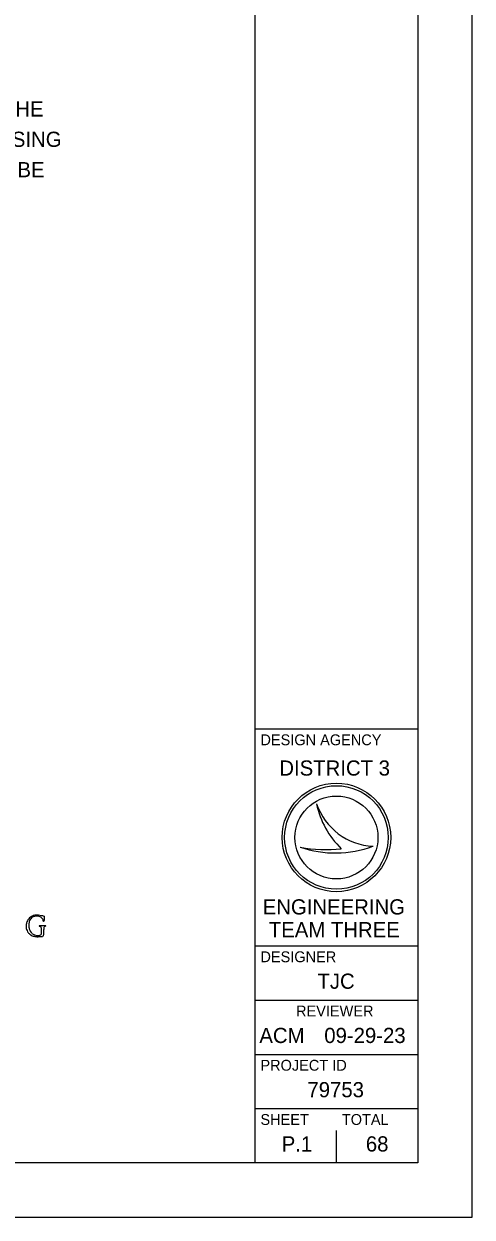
# Model space of a CAD drawing. Extents: x 0 to 34, y 0 to 22.
# Drawn here: x 29.87 to 34, y 0 to 11 of the extents above; entities that cross this region are included whole.
import ezdxf

# ---------------------------------------------------------------- set-up
doc = ezdxf.new("R2010")
doc.units = 0
for name, color, linetype in [('SH_Border', 7, 'Continuous'), ('SH_Cut_Line', 7, 'Continuous'), ('SH_Data', 7, 'Continuous'), ('SH_Text', 7, 'Continuous')]:
    doc.layers.add(name, color=color, linetype=linetype)

msp = doc.modelspace()

# ---------------------------------------------------------------- linework, layer by layer
at = {"layer": 'SH_Border'}
for p, q in [((32, 0.5), (32, 21.5)), ((32, 4.5), (33.5, 4.5)), ((32, 2.5), (33.5, 2.5)), ((32, 2), (33.5, 2)), ((32, 1.5), (33.5, 1.5)), ((32, 1), (33.5, 1))]:
    msp.add_line(p, q, dxfattribs=at)
msp.add_lwpolyline([(1.5, 21.5), (33.5, 21.5), (33.5, 0.5), (1.5, 0.5)], close=True, dxfattribs=at)
at = {"layer": 'SH_Cut_Line'}
msp.add_lwpolyline([(0, 0), (34, 0), (34, 22), (0, 22)], close=True, dxfattribs=at)
at = {"layer": 'SH_Data'}
for p, q in [((32.567, 3.81), (32.567, 3.81)), ((32.75, 3.5), (32.75, 3.5)), ((33.087, 3.419), (33.087, 3.419)), ((32.417, 3.41), (32.417, 3.41)), ((32.75, 0.5), (32.75, 0.8)), ((32.375, 0.675), (32.375, 0.675))]:
    msp.add_line(p, q, dxfattribs=at)
for radius in [0.5, 0.477, 0.477, 0.382]:
    msp.add_circle((32.75, 3.5), radius, dxfattribs=at)
for centre, radius, start, end in [((33.116, 3.998), 0.58, 198.9257, 198.9319), ((33.347, 3.97), 0.796, 191.6379, 191.6421), ((33.116, 3.998), 0.58, 198.9319, 267.1657), ((33.347, 3.97), 0.796, 191.6421, 226.0947), ((32.739, 4.37), 1.013, 251.4576, 290.0832), ((32.648, 4.654), 1.266, 259.4964, 259.4995), ((32.739, 4.37), 1.013, 251.4527, 251.4576), ((32.648, 4.654), 1.266, 259.4995, 276.6672)]:
    msp.add_arc(centre, radius, start, end, dxfattribs=at)
at = {"layer": 'SH_Text'}
for p, q in [((30.072, 2.685), (30.014, 2.685)), ((30.031, 2.666), (30.031, 2.61)), ((30.054, 2.605), (30.054, 2.652))]:
    msp.add_line(p, q, dxfattribs=at)
for centre, radius, start, end in [((30.005, 2.676), 0.116, 135.2994, 157.2066), ((29.985, 2.697), 0.0867, 107.613, 135.2994), ((29.989, 2.705), 0.0714, 116.7026, 147.5385), ((29.983, 2.716), 0.0589, 93.5922, 116.7026), ((29.986, 2.692), 0.0916, 90.0889, 107.613), ((29.99, 2.603), 0.172, 87.6816, 93.5922), ((29.986, 2.53), 0.254, 85.6243, 90.0889), ((29.995, 2.724), 0.0509, 59.809, 87.6816), ((29.987, 2.54), 0.243, 73.3259, 85.6243), ((29.962, 2.667), 0.117, 52.0865, 59.809), ((30.01, 2.729), 0.0384, 2.9119, 52.0865), ((30.056, 2.769), 0.00494, 1.0594, 73.3259), ((29.858, 2.765), 0.203, 350.1479, 1.0594), ((29.983, 2.681), 0.0913, 176.8679, 187.4835), ((30.032, 2.678), 0.141, 167.8164, 176.8679), ((29.97, 2.679), 0.0789, 187.4835, 199.5864), ((29.961, 2.694), 0.0685, 158.442, 167.8164), ((30.038, 2.703), 0.151, 199.5864, 208.6065), ((30.005, 2.676), 0.116, 157.2066, 158.442), ((30.058, 2.688), 0.142, 167.8795, 178.2857), ((30.014, 2.69), 0.0979, 178.2857, 190.5998), ((30.148, 2.715), 0.235, 190.5998, 194.5022), ((30.025, 2.696), 0.108, 165.5071, 167.8795), ((29.989, 2.705), 0.0714, 147.5385, 165.5071), ((30, 2.677), 0.0818, 194.5022, 227.8932), ((30.014, 2.683), 0.00203, 90, 277.32), ((30.016, 2.666), 0.0146, 0, 97.32), ((30.053, 2.731), 0.00447, 182.9119, 350.1479), ((30.213, 2.652), 0.159, 172.0456, 180), ((30.062, 2.674), 0.00585, 114.8736, 172.0456), ((30.069, 2.657), 0.0242, 95.8947, 114.8736), ((30.085, 2.508), 0.174, 94.3316, 95.8947), ((30.072, 2.683), 0.00179, 274.3316, 90), ((29.977, 2.67), 0.0815, 208.6065, 229.3453), ((29.999, 2.696), 0.115, 229.3453, 237.7571), ((29.974, 2.657), 0.0686, 237.7571, 254.2366), ((29.996, 2.672), 0.0755, 227.8932, 268.7516), ((29.992, 2.72), 0.134, 254.2366, 269.1033), ((29.995, 2.891), 0.306, 269.1033, 278.6618), ((29.996, 2.671), 0.075, 268.7516, 293.6665), ((30.023, 2.61), 0.00829, 293.6665, 0), ((30.038, 2.605), 0.016, 278.6618, 0)]:
    msp.add_arc(centre, radius, start, end, dxfattribs=at)

# ---------------------------------------------------------------- texts
at = {"layer": 'SH_Data'}
for s, height, p in [('DESIGN AGENCY', 0.1, (32.05, 4.35)), ('DISTRICT 3', 0.14, (32.224, 4.07)), ('ENGINEERING', 0.14, (32.071, 2.79)), ('TEAM THREE', 0.14, (32.127, 2.58)), ('DESIGNER', 0.1, (32.05, 2.35)), ('TJC', 0.14, (32.575, 2.105)), ('REVIEWER', 0.1, (32.378, 1.85)), ('ACM', 0.14, (32.04, 1.605)), ('09-29-23', 0.14, (32.638, 1.605)), ('PROJECT ID', 0.1, (32.05, 1.35)), ('79753', 0.14, (32.483, 1.105)), ('SHEET', 0.1, (32.05, 0.85)), ('TOTAL', 0.1, (32.8, 0.85)), ('P.1', 0.14, (32.246, 0.605)), ('68', 0.14, (33.021, 0.605))]:
    msp.add_text(s, height=height, dxfattribs=at).set_placement(p)
at = {"layer": 'SH_Text'}
for s, p in [('I HEREBY APPROVE THESE PLANS AND DECLARE THAT THE', (24.528, 10.146)), ('MAKING OF THIS IMPROVEMENT WILL REQUIRE THE CLOSING', (24.528, 9.866)), ('TO TRAFFIC OF THE HIGHWAY AND THAT DETOURS WILL BE', (24.528, 9.586))]:
    msp.add_text(s, height=0.14, dxfattribs=at).set_placement(p)

doc.saveas('drawing.dxf')
